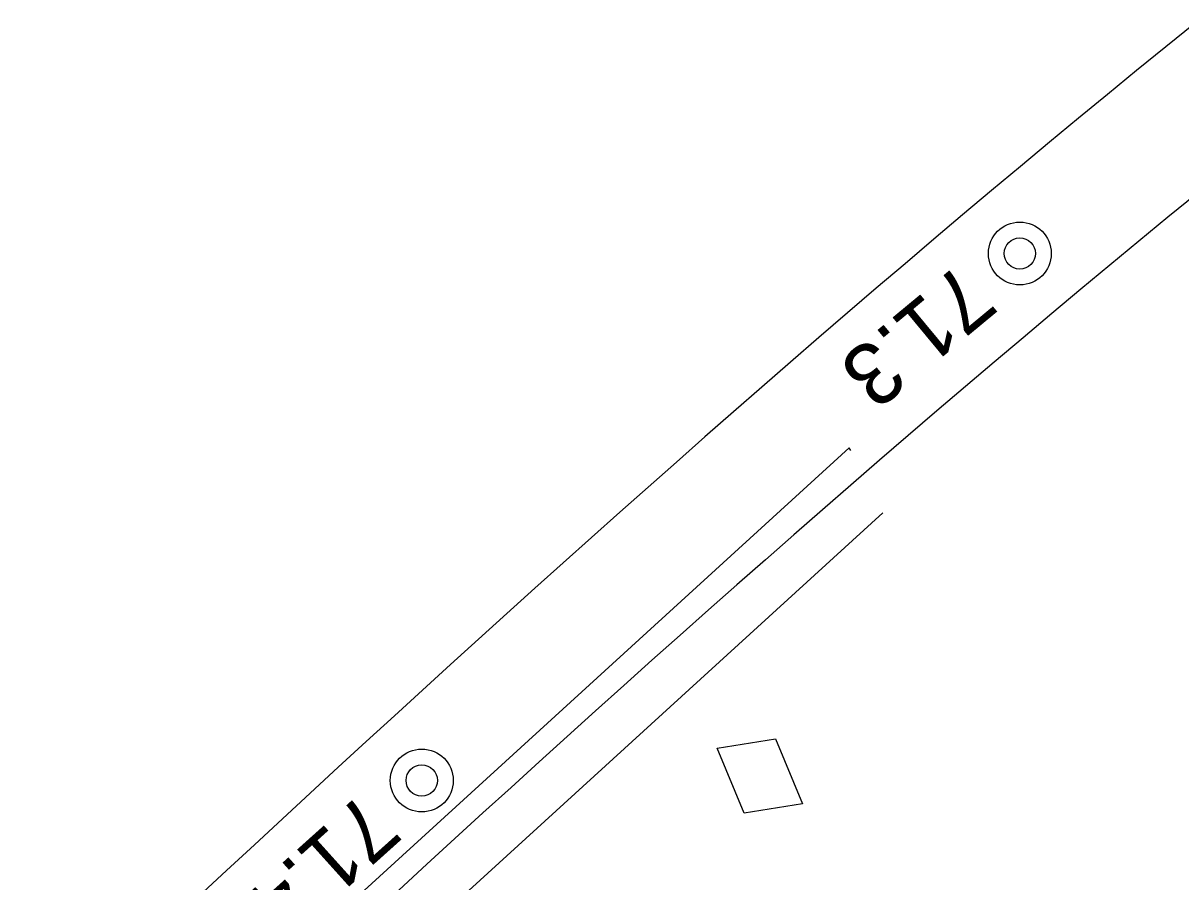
# Model space of a CAD drawing. Extents: x 6541740 to 6556805, y 5525233 to 5530361.
# Drawn here: x 6554777.4 to 6554814.56, y 5525642.69 to 5525670.27 of the extents above; entities that cross this region are included whole.
import ezdxf

# ---------------------------------------------------------------- set-up
doc = ezdxf.new("R2010")
doc.units = 0
for name, color, linetype in [('Default', 7, 'Continuous'), ('TOR_SCH-budynki', 7, 'Continuous'), ('TOR_SCH-hektometry', 7, 'Continuous'), ('TOR_SCH-obiekty projektowane', 7, 'Continuous'), ('TOR_SCH-tory projektowane', 7, 'Continuous')]:
    doc.layers.add(name, color=color, linetype=linetype)

# ---------------------------------------------------------------- blocks, each defined once
blk = doc.blocks.new('4010_1')
at = {"layer": 'Default'}
for radius in [0.75, 0.375]:
    blk.add_circle((0, 0), radius, dxfattribs=at)

msp = doc.modelspace()

# ---------------------------------------------------------------- linework, layer by layer
at = {"layer": 'TOR_SCH-budynki'}
for p, q in [((6554799.681, 5525646.981), (6554801.553, 5525647.276)), ((6554801.553, 5525647.276), (6554802.417, 5525645.191)), ((6554800.542, 5525644.897), (6554799.681, 5525646.981)), ((6554802.417, 5525645.191), (6554800.542, 5525644.897))]:
    msp.add_line(p, q, dxfattribs=at)
at = {"layer": 'TOR_SCH-obiekty projektowane'}
for p, q in [((6554777.395, 5525632.425), (6554803.914, 5525656.626)), ((6554803.966, 5525656.541), (6554803.914, 5525656.626)), ((6554778.474, 5525630.339), (6554804.994, 5525654.54))]:
    msp.add_line(p, q, dxfattribs=at)
at = {"layer": 'TOR_SCH-tory projektowane'}
for points in [[(6554815.019, 5525670.27), (6554814.08, 5525669.511), (6554813.143, 5525668.749), (6554812.208, 5525667.983), (6554811.274, 5525667.215), (6554810.342, 5525666.443), (6554809.412, 5525665.669), (6554808.484, 5525664.892), (6554807.557, 5525664.112), (6554806.632, 5525663.329), (6554805.708, 5525662.544), (6554804.786, 5525661.756), (6554803.865, 5525660.966), (6554802.946, 5525660.173), (6554802.028, 5525659.378), (6554801.112, 5525658.58), (6554800.197, 5525657.78), (6554799.283, 5525656.977), (6554798.371, 5525656.173), (6554797.46, 5525655.366), (6554796.55, 5525654.558), (6554795.641, 5525653.747), (6554794.734, 5525652.934), (6554793.828, 5525652.12), (6554792.923, 5525651.303), (6554792.019, 5525650.485), (6554791.116, 5525649.665), (6554790.214, 5525648.843), (6554789.313, 5525648.02), (6554788.412, 5525647.195), (6554787.513, 5525646.368), (6554786.615, 5525645.54), (6554785.718, 5525644.711), (6554784.821, 5525643.88), (6554783.925, 5525643.049), (6554783.03, 5525642.215)], [(6554815.087, 5525664.803), (6554814.151, 5525664.038), (6554813.218, 5525663.269), (6554812.286, 5525662.498), (6554811.356, 5525661.724), (6554810.427, 5525660.947), (6554809.5, 5525660.167), (6554808.575, 5525659.385), (6554807.651, 5525658.599), (6554806.729, 5525657.812), (6554805.808, 5525657.021), (6554804.889, 5525656.229), (6554803.971, 5525655.433), (6554803.054, 5525654.636), (6554802.139, 5525653.836), (6554801.226, 5525653.033), (6554800.313, 5525652.229), (6554799.402, 5525651.422), (6554798.492, 5525650.614), (6554797.584, 5525649.803), (6554796.676, 5525648.99), (6554795.77, 5525648.176), (6554794.865, 5525647.359), (6554793.961, 5525646.541), (6554793.058, 5525645.721), (6554792.156, 5525644.9), (6554791.255, 5525644.076), (6554790.355, 5525643.251), (6554789.455, 5525642.425)]]:
    msp.add_lwpolyline(points, dxfattribs=at)

# ---------------------------------------------------------------- block references
at = {"layer": 'TOR_SCH-hektometry'}
for p, xscale, yscale, rotation in [((6554809.394, 5525662.871), 1.3459632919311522, 1.3459632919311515, 13.29011517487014), ((6554790.193, 5525645.943), 1.3459632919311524, 1.345963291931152, 15.576997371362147)]:
    msp.add_blockref('4010_1', p, dxfattribs=dict(at, xscale=xscale, yscale=yscale, rotation=rotation))

# ---------------------------------------------------------------- texts
for s, rotation, p in [('71.3', 219.6694, (6554807.498, 5525662.632)), ('71.4', 221.9562, (6554788.306, 5525645.627))]:
    msp.add_text(s, height=2, rotation=rotation, dxfattribs=at).set_placement(p)

doc.saveas('drawing.dxf')
